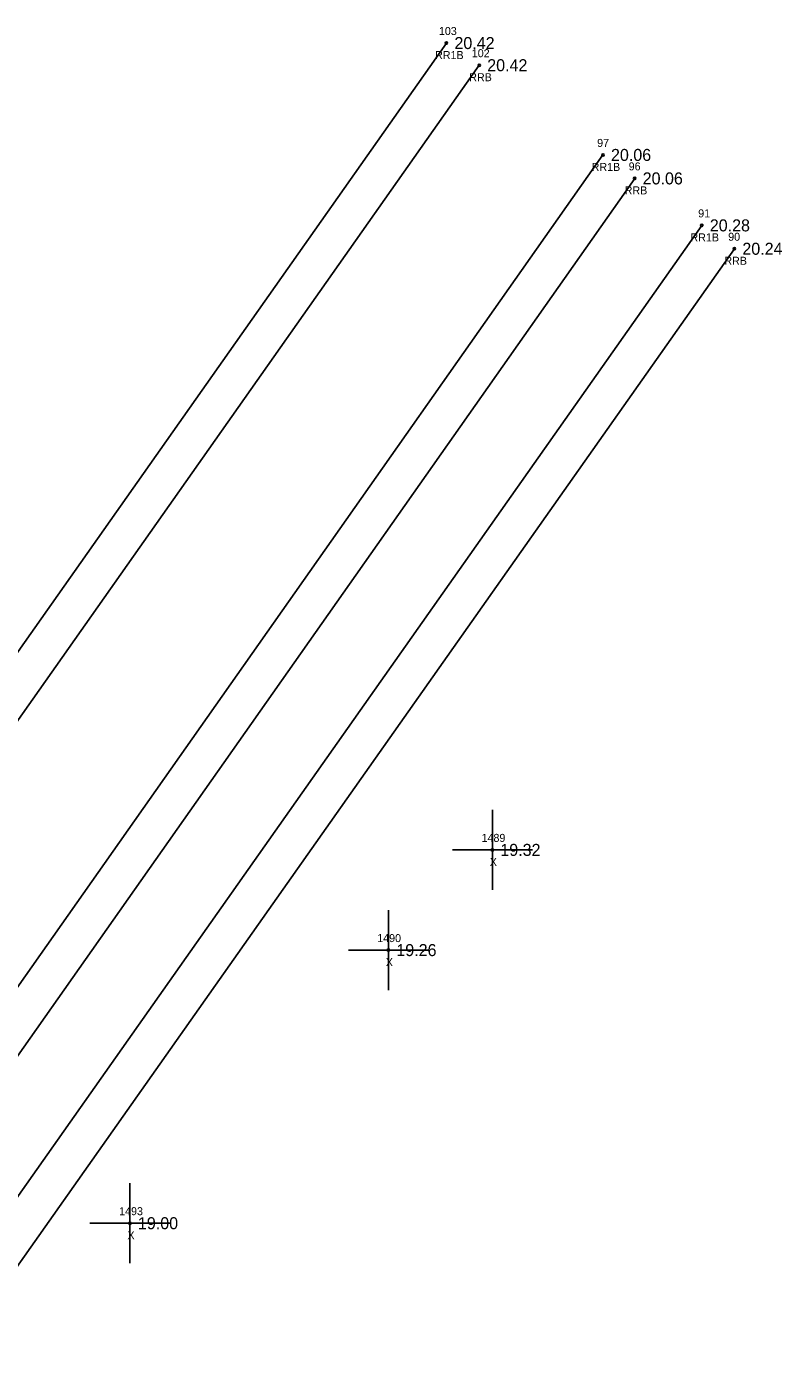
# Model space of a CAD drawing. Extents: x 2042211 to 2045853, y 303080 to 309569.
# Drawn here: x 2043522.3 to 2043616.7, y 305889.6 to 306057.8 of the extents above; entities that cross this region are included whole.
import ezdxf

# ---------------------------------------------------------------- set-up
doc = ezdxf.new("R2010")
doc.units = 0
for name, color, linetype in [('RD_EX_Misc', 7, 'Continuous'), ('RD_EX_Misc_txCode', 7, 'Continuous'), ('RD_EX_RailRoad', 7, 'Continuous'), ('RD_EX_RailRoad_txCode', 7, 'Continuous'), ('RD_EX_TX_Misc_ELEV', 7, 'Continuous'), ('RD_EX_TX_RailRoad_ELEV', 7, 'Continuous'), ('RD_SMD_Locator', 7, 'Continuous')]:
    doc.layers.add(name, color=color, linetype=linetype)

msp = doc.modelspace()

# ---------------------------------------------------------------- linework, layer by layer
at = {"layer": 'RD_EX_Misc'}
for p, q in [((2043580.5, 305950), (2043580.5, 305960)), ((2043575.5, 305955), (2043585.5, 305955)), ((2043567.5, 305937.48), (2043567.5, 305947.48)), ((2043562.5, 305942.48), (2043572.5, 305942.48)), ((2043535.2, 305903.36), (2043535.2, 305913.36)), ((2043530.2, 305908.36), (2043540.2, 305908.36))]:
    msp.add_line(p, q, dxfattribs=at)
at = {"layer": 'RD_EX_RailRoad'}
for points in [[(2043316.98, 305689.81), (2043465.55, 305900.81), (2043574.76, 306055.8)], [(2043321.05, 305686.98), (2043469.61, 305897.99), (2043578.86, 306053.03)], [(2043362.26, 305712.2), (2043485.47, 305887.19), (2043594.33, 306041.82)], [(2043366.36, 305709.46), (2043489.69, 305884.58), (2043598.29, 306038.89)], [(2043374.76, 305703.68), (2043497.91, 305878.7), (2043606.68, 306033.02)], [(2043378.92, 305700.92), (2043501.99, 305875.87), (2043610.75, 306030.1)]]:
    msp.add_lwpolyline(points, dxfattribs=at)
at = {"layer": 'RD_SMD_Locator'}
for centre in [(2043574.76, 306055.8), (2043578.86, 306053.03), (2043594.33, 306041.82), (2043598.29, 306038.89), (2043606.68, 306033.02), (2043610.75, 306030.1), (2043580.5, 305955), (2043567.5, 305942.48), (2043535.2, 305908.36)]:
    msp.add_circle(centre, 0.15, dxfattribs=at)

# ---------------------------------------------------------------- texts
at = {"layer": 'RD_EX_Misc_txCode'}
for s, p in [('1489', (2043579.15, 305956)), ('X', (2043580.18, 305953)), ('1490', (2043566.11, 305943.48)), ('X', (2043567.18, 305940.48)), ('1493', (2043533.85, 305909.36)), ('X', (2043534.89, 305906.36))]:
    msp.add_text(s, height=1, dxfattribs=at).set_placement(p)
at = {"layer": 'RD_EX_RailRoad_txCode'}
for s, p in [('103', (2043573.82, 306056.8)), ('RR1B', (2043573.34, 306053.8)), ('102', (2043577.93, 306054.03)), ('RRB', (2043577.61, 306051.03)), ('97', (2043593.6, 306042.82)), ('96', (2043597.54, 306039.89)), ('RR1B', (2043592.91, 306039.82)), ('RRB', (2043597.04, 306036.89)), ('91', (2043606.23, 306034.02)), ('RR1B', (2043605.26, 306031.02)), ('90', (2043609.98, 306031.1)), ('RRB', (2043609.5, 306028.1))]:
    msp.add_text(s, height=1, dxfattribs=at).set_placement(p)
at = {"layer": 'RD_EX_TX_Misc_ELEV'}
for s, p in [('19.32', (2043581.5, 305954.25)), ('19.26', (2043568.5, 305941.73)), ('19.00', (2043536.2, 305907.61))]:
    msp.add_text(s, height=1.5, dxfattribs=at).set_placement(p)
at = {"layer": 'RD_EX_TX_RailRoad_ELEV'}
for s, p in [('20.42', (2043575.76, 306055.05)), ('20.42', (2043579.86, 306052.28)), ('20.06', (2043595.33, 306041.07)), ('20.06', (2043599.29, 306038.14)), ('20.28', (2043607.68, 306032.27)), ('20.24', (2043611.75, 306029.35))]:
    msp.add_text(s, height=1.5, dxfattribs=at).set_placement(p)

doc.saveas('drawing.dxf')
